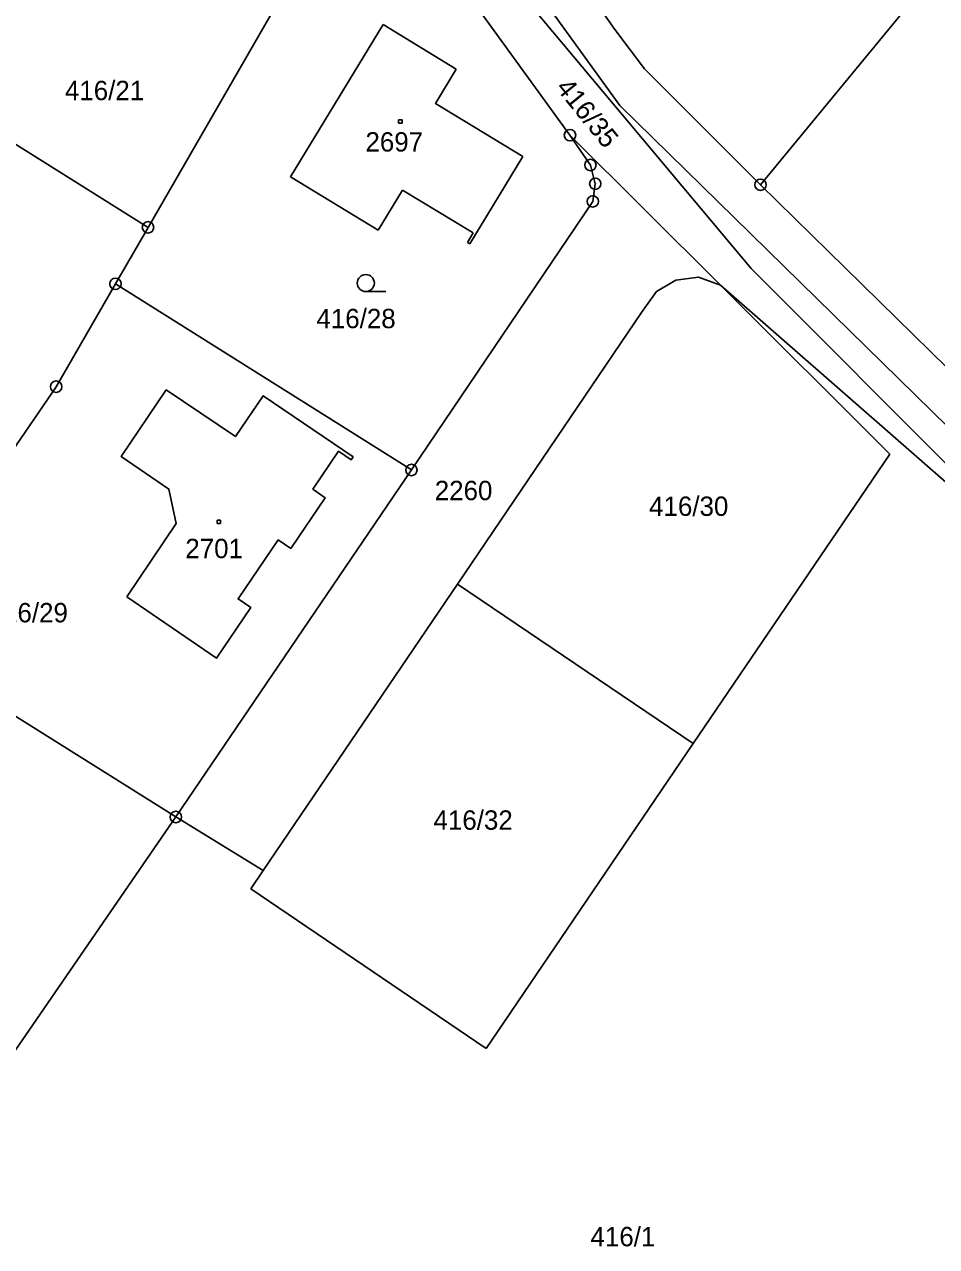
# Model space of a CAD drawing. Extents: x -795483 to -789093, y -1112258 to -1108741.
# Drawn here: x -791181.5 to -791101.5, y -1111107.3 to -1111000 of the extents above; entities that cross this region are included whole.
import ezdxf

# ---------------------------------------------------------------- set-up
doc = ezdxf.new("R2010")
doc.units = 0
for name, color, linetype in [('Vrstva 1', 7, 'Continuous'), ('Vrstva 14', 7, 'Continuous'), ('Vrstva 15', 7, 'Continuous'), ('Vrstva 23', 7, 'Continuous'), ('Vrstva 25', 7, 'Continuous'), ('Vrstva 28', 7, 'Continuous')]:
    doc.layers.add(name, color=color, linetype=linetype)

msp = doc.modelspace()

# ---------------------------------------------------------------- linework, layer by layer
at = {"layer": 'Vrstva 1'}
for p, q in [((-791090.03, -1110981.39), (-791116.94, -1111014.08)), ((-791129.27, -1111007.14), (-791146.11, -1110983.83)), ((-791151.67, -1110984.9), (-791170.66, -1111017.82)), ((-791133.65, -1111009.73), (-791151.67, -1110984.9)), ((-791144.69, -1110989.26), (-791117.77, -1111021.44)), ((-791136.45, -1110990.81), (-791129.72, -1111000.47)), ((-791170.66, -1111017.82), (-791199.85, -1110999.51)), ((-791158.16, -1111013.4), (-791150.05, -1111000.02)), ((-791150.05, -1111000.02), (-791143.62, -1111003.95)), ((-791129.72, -1111000.47), (-791127.11, -1111003.91)), ((-791127.11, -1111003.91), (-791116.94, -1111014.08)), ((-791096.5, -1111039.26), (-791129.27, -1111007.14)), ((-791131.86, -1111012.35), (-791133.65, -1111009.73)), ((-791120.44, -1111022.9), (-791133.65, -1111009.73)), ((-791137.79, -1111011.6), (-791142.44, -1111019.28)), ((-791131.43, -1111013.99), (-791131.86, -1111012.35)), ((-791150.48, -1111018.06), (-791158.16, -1111013.4)), ((-791148.35, -1111014.55), (-791150.48, -1111018.06)), ((-791142.15, -1111018.31), (-791148.35, -1111014.55)), ((-791131.65, -1111015.54), (-791131.43, -1111013.99)), ((-791116.94, -1111014.08), (-791094.58, -1111036.03)), ((-791147.56, -1111039.11), (-791131.65, -1111015.54)), ((-791170.66, -1111017.82), (-791173.52, -1111022.78)), ((-791142.65, -1111019.15), (-791142.15, -1111018.31)), ((-791142.44, -1111019.28), (-791142.65, -1111019.15)), ((-791117.77, -1111021.44), (-791096.96, -1111042.29)), ((-791173.52, -1111022.78), (-791147.56, -1111039.11)), ((-791124.36, -1111022.44), (-791126.05, -1111023.44)), ((-791122.39, -1111022.19), (-791124.36, -1111022.44)), ((-791120.44, -1111022.9), (-791122.39, -1111022.19)), ((-791120.44, -1111022.9), (-791095.82, -1111044.46)), ((-791105.6, -1111037.71), (-791120.44, -1111022.9)), ((-791126.05, -1111023.44), (-791127.37, -1111025.29)), ((-791143.51, -1111049.12), (-791127.37, -1111025.29)), ((-791122.83, -1111063.1), (-791105.6, -1111037.71)), ((-791147.56, -1111039.11), (-791168.22, -1111069.56)), ((-791143.51, -1111049.12), (-791160.55, -1111074.25)), ((-791143.51, -1111049.12), (-791122.83, -1111063.1)), ((-791168.22, -1111069.56), (-791193.64, -1111053.6)), ((-791141, -1111089.88), (-791122.83, -1111063.1)), ((-791168.22, -1111069.56), (-791185.22, -1111094.26)), ((-791160.55, -1111074.25), (-791168.22, -1111069.56)), ((-791160.55, -1111074.25), (-791161.65, -1111075.86)), ((-791161.65, -1111075.86), (-791141, -1111089.88))]:
    msp.add_line(p, q, dxfattribs=at)
for points in [[(-791143.62, -1111003.95), (-791145.44, -1111006.94), (-791137.79, -1111011.6)], [(-791184.18, -1111039.78), (-791178.72, -1111031.8), (-791173.52, -1111022.78)], [(-791172.53, -1111050.25), (-791168.19, -1111043.82), (-791168.83, -1111040.78), (-791173.02, -1111037.92), (-791169.06, -1111032.08), (-791162.99, -1111036.18), (-791160.55, -1111032.6), (-791152.68, -1111037.96), (-791152.84, -1111038.21), (-791153.94, -1111037.46), (-791156.2, -1111040.79), (-791155.11, -1111041.56), (-791158.14, -1111046), (-791159.24, -1111045.24), (-791162.76, -1111050.43), (-791161.65, -1111051.19), (-791164.66, -1111055.63), (-791172.53, -1111050.25)]]:
    msp.add_lwpolyline(points, dxfattribs=at)
at = {"layer": 'Vrstva 23'}
msp.add_line((-791151.56, -1111023.46), (-791149.81, -1111023.46), dxfattribs=at)
msp.add_circle((-791151.56, -1111022.71), 0.75, dxfattribs=at)
at = {"layer": 'Vrstva 25'}
for p, q in [((-791148.68, -1111008.38), (-791148.38, -1111008.38)), ((-791148.68, -1111008.68), (-791148.68, -1111008.38)), ((-791148.38, -1111008.68), (-791148.68, -1111008.68)), ((-791148.38, -1111008.38), (-791148.38, -1111008.68)), ((-791164.61, -1111043.5), (-791164.31, -1111043.5)), ((-791164.61, -1111043.8), (-791164.61, -1111043.5)), ((-791164.31, -1111043.5), (-791164.31, -1111043.8)), ((-791164.31, -1111043.8), (-791164.61, -1111043.8))]:
    msp.add_line(p, q, dxfattribs=at)
at = {"layer": 'Vrstva 28'}
for centre, radius in [((-791133.65, -1111009.73), 0.5), ((-791133.65, -1111009.73), 0.01), ((-791131.86, -1111012.35), 0.5), ((-791131.86, -1111012.35), 0.01), ((-791131.43, -1111013.99), 0.5), ((-791131.43, -1111013.99), 0.01), ((-791116.94, -1111014.08), 0.5), ((-791116.94, -1111014.08), 0.01), ((-791131.65, -1111015.54), 0.5), ((-791131.65, -1111015.54), 0.01), ((-791170.66, -1111017.82), 0.5), ((-791170.66, -1111017.82), 0.01), ((-791173.52, -1111022.78), 0.5), ((-791173.52, -1111022.78), 0.01), ((-791178.72, -1111031.8), 0.5), ((-791178.72, -1111031.8), 0.01), ((-791147.56, -1111039.11), 0.5), ((-791147.56, -1111039.11), 0.01), ((-791168.22, -1111069.56), 0.5), ((-791168.22, -1111069.56), 0.01)]:
    msp.add_circle(centre, radius, dxfattribs=at)

# ---------------------------------------------------------------- texts
at = {"layer": 'Vrstva 14'}
for s, p in [('416/21', (-791177.95, -1111006.66)), ('416/28', (-791155.89, -1111026.67)), ('2260', (-791145.51, -1111041.76)), ('416/30', (-791126.71, -1111043.14)), ('416/29', (-791184.64, -1111052.48)), ('416/32', (-791145.62, -1111070.68)), ('416/1', (-791131.85, -1111107.23))]:
    msp.add_text(s, height=1.7, dxfattribs=at).set_placement(p)
msp.add_text('416/35', height=1.7, rotation=309.0257, dxfattribs=at).set_placement((-791134.96, -1111005.6))
at = {"layer": 'Vrstva 15'}
for s, p in [('2697', (-791151.59, -1111011.17)), ('2701', (-791167.39, -1111046.85))]:
    msp.add_text(s, height=1.7, dxfattribs=at).set_placement(p)

doc.saveas('drawing.dxf')
